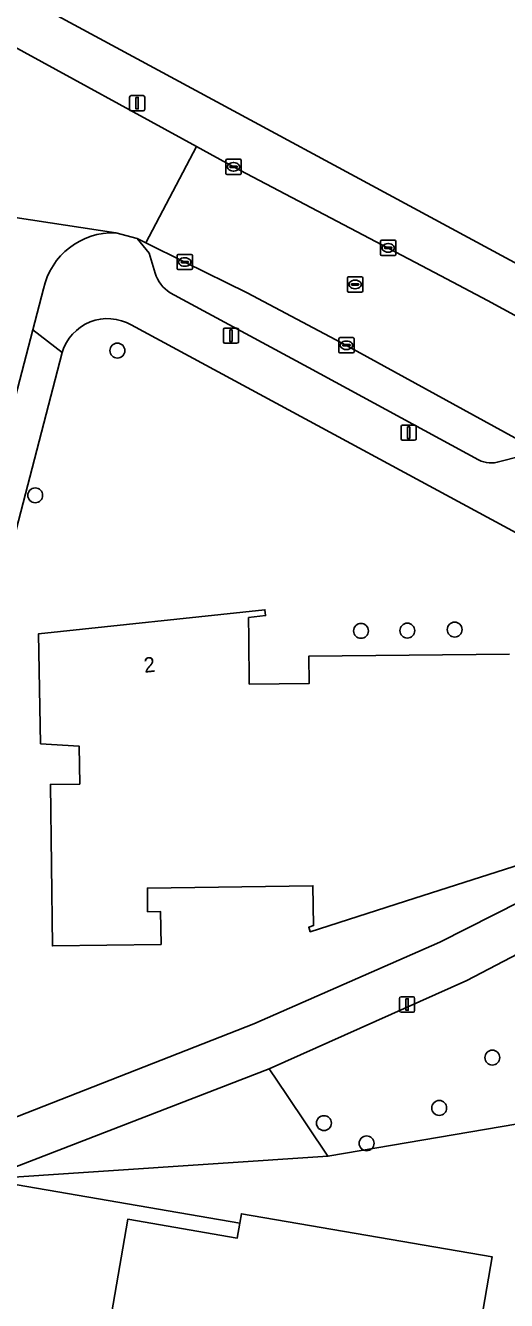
# Model space of a CAD drawing. Extents: x 161258 to 161838, y 380833 to 381727.
# Drawn here: x 161624.3 to 161655.9, y 381007.6 to 381091.2 of the extents above; entities that cross this region are included whole.
import ezdxf

# ---------------------------------------------------------------- set-up
doc = ezdxf.new("R2010")
doc.units = 0
for name, color, linetype in [('IMGEO_Boom', 7, 'Continuous'), ('IMGEO_Erf', 7, 'Continuous'), ('IMGEO_Fietspad_gesloten', 7, 'Continuous'), ('IMGEO_Groenvoorziening', 7, 'Continuous'), ('IMGEO_Kolk', 7, 'Continuous'), ('IMGEO_Lichtmast', 7, 'Continuous'), ('IMGEO_Pand', 7, 'Continuous'), ('IMGEO_Pand_nummerreeks', 7, 'Continuous'), ('IMGEO_Pand_overbouw', 7, 'Continuous'), ('IMGEO_Parkeervlak_open', 7, 'Continuous'), ('IMGEO_Rijbaan_lokaal_open', 7, 'Continuous'), ('IMGEO_Rioolput', 7, 'Continuous'), ('IMGEO_Voetpad_open', 7, 'Continuous')]:
    doc.layers.add(name, color=color, linetype=linetype)

msp = doc.modelspace()

# ---------------------------------------------------------------- linework, layer by layer
at = {"layer": 'IMGEO_Boom'}
for centre in [(161630.384, 381069.91), (161624.985, 381060.41), (161646.377, 381051.519), (161649.42, 381051.535), (161652.532, 381051.604), (161655.003, 381023.517), (161651.513, 381020.212), (161643.944, 381019.216), (161646.745, 381017.89)]:
    msp.add_circle(centre, 0.489, dxfattribs=at)
at = {"layer": 'IMGEO_Erf'}
for points in [[(161599.292, 381107.15), (161603.367, 381104.463), (161608.252, 381101.703), (161676.825, 381064.703), (161683.729, 381060.833), (161686.794, 381059.495), (161691.724, 381057.608), (161696.114, 381056.287), (161709.767, 381053.57)], [(161675.471, 381050.931), (161664.588, 381056.855), (161662.556, 381054.709), (161631.294, 381071.59)], [(161626.757, 381069.781), (161616.62, 381030.824), (161615.408, 381026.168), (161614.162, 381021.378)], [(161662.306, 381037.947), (161649.92, 381033.973), (161643.044, 381031.769), (161642.947, 381032.074), (161643.261, 381032.174), (161643.217, 381034.788), (161632.354, 381034.635), (161632.37, 381033.087), (161633.22, 381033.1), (161633.254, 381030.942), (161626.113, 381030.848), (161625.982, 381041.445), (161627.912, 381041.469), (161627.879, 381043.946), (161625.335, 381044.112), (161625.192, 381051.313), (161640.074, 381052.905), (161640.116, 381052.521), (161639, 381052.39), (161639.011, 381051.044), (161639.037, 381048.03), (161642.977, 381048.072), (161642.958, 381049.862), (161656.14, 381049.999)], [(161688.26, 381045.583), (161687.06, 381041.825), (161684.086, 381036.733), (161672.137, 381030.317), (161666.141, 381026.08), (161661.136, 381022.555), (161659.038, 381021.802), (161658.733, 381019.525), (161644.202, 381017.041), (161621.594, 381015.546), (161621.493, 381015.508), (161609.322, 381011.183), (161608.503, 381011.142), (161603.457, 381003.135)], [(161621.073, 381018.632), (161622.189, 381019.011), (161639.35, 381025.737), (161651.548, 381031.097), (161656.876, 381033.773)], [(161630.098, 381007.334), (161631.061, 381012.91), (161638.251, 381011.67), (161638.42, 381012.654), (161638.525, 381013.267), (161654.985, 381010.445), (161649.385, 380977.871)]]:
    msp.add_lwpolyline(points, dxfattribs=at)
msp.add_arc((161629.736, 381068.903), 3.106, 59.89964, 163.57684, dxfattribs=at)
at = {"layer": 'IMGEO_Fietspad_gesloten'}
for points in [[(161630.283, 381077.643), (161623.675, 381078.64), (161622.285, 381073.268), (161614.192, 381041.977), (161611.518, 381032.045)], [(161614.41, 381031.306), (161624.834, 381071.281), (161625.531, 381073.954)]]:
    msp.add_lwpolyline(points, dxfattribs=at)
msp.add_arc((161630.103, 381072.97), 4.676, 87.79003, 167.85469, dxfattribs=at)
at = {"layer": 'IMGEO_Groenvoorziening'}
msp.add_lwpolyline([(161679.02, 381046.972), (161678.939, 381046.842), (161676.868, 381044.169), (161675.516, 381042.671), (161671.619, 381039.336), (161668.104, 381036.84), (161665.195, 381035.022), (161660.071, 381032.09), (161653.332, 381028.579), (161640.355, 381022.779), (161641.485, 381021.093), (161644.202, 381017.041), (161658.733, 381019.525), (161659.038, 381021.802), (161661.136, 381022.555), (161666.141, 381026.08), (161672.137, 381030.317), (161684.086, 381036.733)], dxfattribs=at)
msp.add_lwpolyline([(161641.485, 381021.093), (161640.355, 381022.779), (161621.594, 381015.546), (161644.202, 381017.041)], close=True, dxfattribs=at)
at = {"layer": 'IMGEO_Kolk'}
for p, q in [((161637.508, 381081.541), (161637.508, 381082.393)), ((161637.583, 381082.467), (161638.435, 381082.467)), ((161637.767, 381081.961), (161637.767, 381081.973)), ((161638.205, 381081.924), (161637.807, 381081.924)), ((161637.81, 381082.01), (161638.208, 381082.01)), ((161637.996, 381082.247), (161638.021, 381082.247)), ((161638.251, 381081.973), (161638.251, 381081.961)), ((161638.509, 381082.393), (161638.509, 381081.541)), ((161638.435, 381081.467), (161637.583, 381081.467)), ((161638.019, 381081.687), (161637.994, 381081.687)), ((161647.664, 381076.221), (161647.664, 381077.073)), ((161647.739, 381077.147), (161648.591, 381077.147)), ((161648.152, 381076.927), (161648.177, 381076.927)), ((161648.665, 381077.073), (161648.665, 381076.221)), ((161634.306, 381075.296), (161634.306, 381076.148)), ((161634.381, 381076.222), (161635.233, 381076.222)), ((161634.794, 381076.002), (161634.819, 381076.002)), ((161635.307, 381076.148), (161635.307, 381075.296)), ((161648.591, 381076.147), (161647.739, 381076.147)), ((161647.923, 381076.641), (161647.923, 381076.653)), ((161648.361, 381076.604), (161647.963, 381076.604)), ((161647.966, 381076.69), (161648.364, 381076.69)), ((161648.175, 381076.367), (161648.15, 381076.367)), ((161648.407, 381076.653), (161648.407, 381076.641)), ((161635.233, 381075.222), (161634.381, 381075.222)), ((161634.565, 381075.716), (161634.565, 381075.728)), ((161635.003, 381075.679), (161634.605, 381075.679)), ((161634.608, 381075.765), (161635.006, 381075.765)), ((161634.817, 381075.442), (161634.792, 381075.442)), ((161635.049, 381075.728), (161635.049, 381075.716)), ((161644.922, 381069.832), (161644.922, 381070.684)), ((161644.997, 381070.758), (161645.849, 381070.758)), ((161645.181, 381070.252), (161645.181, 381070.264)), ((161645.619, 381070.215), (161645.221, 381070.215)), ((161645.224, 381070.301), (161645.622, 381070.301)), ((161645.41, 381070.538), (161645.435, 381070.538)), ((161645.665, 381070.264), (161645.665, 381070.252)), ((161645.923, 381070.684), (161645.923, 381069.832)), ((161645.849, 381069.758), (161644.997, 381069.758)), ((161645.433, 381069.978), (161645.408, 381069.978))]:
    msp.add_line(p, q, dxfattribs=at)
for points in [[(161637.508, 381081.541), (161637.508, 381082.393)], [(161637.583, 381082.467), (161638.435, 381082.467)], [(161638.509, 381082.393), (161638.509, 381081.541)], [(161638.435, 381081.467), (161637.583, 381081.467)], [(161647.664, 381076.221), (161647.664, 381077.073)], [(161647.739, 381077.147), (161648.591, 381077.147)], [(161648.665, 381077.073), (161648.665, 381076.221)], [(161634.306, 381075.296), (161634.306, 381076.148)], [(161634.381, 381076.222), (161635.233, 381076.222)], [(161635.307, 381076.148), (161635.307, 381075.296)], [(161648.591, 381076.147), (161647.739, 381076.147)], [(161635.233, 381075.222), (161634.381, 381075.222)], [(161644.922, 381069.832), (161644.922, 381070.684)], [(161644.997, 381070.758), (161645.849, 381070.758)], [(161645.923, 381070.684), (161645.923, 381069.832)], [(161645.849, 381069.758), (161644.997, 381069.758)]]:
    msp.add_lwpolyline(points, dxfattribs=at)
for centre, radius, start, end in [((161637.585, 381082.391), 0.0765, 91.55205, 178.44795), ((161637.585, 381082.391), 0.0765, 91.55205, 178.44795), ((161637.807, 381081.97), 0.0403, 85.87752, 175.75265), ((161637.804, 381081.96), 0.0366, 178.93798, 274.71019), ((161638.208, 381081.967), 0.043, 264.86636, 352.45326), ((161638.212, 381081.972), 0.0386, 1.73085, 96.63898), ((161638.433, 381082.391), 0.0765, 1.55205, 88.44795), ((161638.433, 381082.391), 0.0765, 1.55205, 88.44795), ((161637.585, 381081.543), 0.0765, 181.55205, 268.44795), ((161637.585, 381081.543), 0.0765, 181.55205, 268.44795), ((161638.433, 381081.543), 0.0765, 271.55205, 358.44795), ((161638.433, 381081.543), 0.0765, 271.55205, 358.44795), ((161647.741, 381077.071), 0.0765, 91.55205, 178.44795), ((161647.741, 381077.071), 0.0765, 91.55205, 178.44795), ((161648.589, 381077.071), 0.0765, 1.55205, 88.44795), ((161648.589, 381077.071), 0.0765, 1.55205, 88.44795), ((161634.383, 381076.146), 0.0765, 91.55205, 178.44795), ((161634.383, 381076.146), 0.0765, 91.55205, 178.44795), ((161635.231, 381076.146), 0.0765, 1.55205, 88.44795), ((161635.231, 381076.146), 0.0765, 1.55205, 88.44795), ((161647.741, 381076.223), 0.0765, 181.55205, 268.44795), ((161647.741, 381076.223), 0.0765, 181.55205, 268.44795), ((161647.963, 381076.65), 0.0403, 85.87752, 175.75265), ((161647.96, 381076.64), 0.0366, 178.93798, 274.71019), ((161648.364, 381076.647), 0.043, 264.86636, 352.45326), ((161648.368, 381076.652), 0.0386, 1.73085, 96.63898), ((161648.589, 381076.223), 0.0765, 271.55205, 358.44795), ((161648.589, 381076.223), 0.0765, 271.55205, 358.44795), ((161634.383, 381075.298), 0.0765, 181.55205, 268.44795), ((161634.383, 381075.298), 0.0765, 181.55205, 268.44795), ((161634.605, 381075.725), 0.0403, 85.87752, 175.75265), ((161634.602, 381075.715), 0.0366, 178.93798, 274.71019), ((161635.006, 381075.722), 0.043, 264.86636, 352.45326), ((161635.01, 381075.727), 0.0386, 1.73085, 96.63898), ((161635.231, 381075.298), 0.0765, 271.55205, 358.44795), ((161635.231, 381075.298), 0.0765, 271.55205, 358.44795), ((161644.999, 381070.682), 0.0765, 91.55205, 178.44795), ((161644.999, 381070.682), 0.0765, 91.55205, 178.44795), ((161645.221, 381070.261), 0.0403, 85.87752, 175.75265), ((161645.218, 381070.251), 0.0366, 178.93798, 274.71019), ((161645.622, 381070.258), 0.043, 264.86636, 352.45326), ((161645.626, 381070.263), 0.0386, 1.73085, 96.63898), ((161645.847, 381070.682), 0.0765, 1.55205, 88.44795), ((161645.847, 381070.682), 0.0765, 1.55205, 88.44795), ((161644.999, 381069.834), 0.0765, 181.55205, 268.44795), ((161644.999, 381069.834), 0.0765, 181.55205, 268.44795), ((161645.847, 381069.834), 0.0765, 271.55205, 358.44795), ((161645.847, 381069.834), 0.0765, 271.55205, 358.44795)]:
    msp.add_arc(centre, radius, start, end, dxfattribs=at)
for centre, major_axis, ratio, start_param, end_param in [((161637.995, 381081.967), (-0.387, 0.002), 0.722429, 4.712389, 7.853982), ((161638.02, 381081.967), (-0.39, 0.002), 0.717154, 1.570796, 4.712389), ((161648.151, 381076.647), (-0.387, 0.002), 0.722429, 4.712389, 7.853982), ((161648.176, 381076.647), (-0.39, 0.002), 0.717154, 1.570796, 4.712389), ((161634.793, 381075.722), (-0.387, 0.002), 0.722429, 4.712389, 7.853982), ((161634.818, 381075.722), (-0.39, 0.002), 0.717154, 1.570796, 4.712389), ((161645.409, 381070.258), (-0.387, 0.002), 0.722429, 4.712389, 7.853982), ((161645.434, 381070.258), (-0.39, 0.002), 0.717154, 1.570796, 4.712389)]:
    msp.add_ellipse(centre, major_axis=major_axis, ratio=ratio, start_param=start_param, end_param=end_param, dxfattribs=at)
at = {"layer": 'IMGEO_Lichtmast'}
for p, q in [((161631.184, 381085.743), (161631.184, 381086.543)), ((161631.184, 381086.543), (161631.184, 381085.743)), ((161631.284, 381086.643), (161632.074, 381086.643)), ((161632.074, 381086.643), (161631.284, 381086.643)), ((161632.174, 381086.543), (161632.174, 381085.743)), ((161632.174, 381085.743), (161632.174, 381086.543)), ((161632.074, 381085.643), (161631.284, 381085.643)), ((161631.284, 381085.643), (161632.074, 381085.643)), ((161637.342, 381070.488), (161637.342, 381071.288)), ((161637.342, 381071.288), (161637.342, 381070.488)), ((161637.442, 381071.388), (161638.232, 381071.388)), ((161638.232, 381071.388), (161637.442, 381071.388)), ((161638.332, 381071.288), (161638.332, 381070.488)), ((161638.332, 381070.488), (161638.332, 381071.288)), ((161638.232, 381070.388), (161637.442, 381070.388)), ((161637.442, 381070.388), (161638.232, 381070.388)), ((161649.011, 381064.121), (161649.011, 381064.921)), ((161649.011, 381064.921), (161649.011, 381064.121)), ((161649.111, 381065.021), (161649.901, 381065.021)), ((161649.901, 381065.021), (161649.111, 381065.021)), ((161650.001, 381064.921), (161650.001, 381064.121)), ((161650.001, 381064.121), (161650.001, 381064.921)), ((161649.901, 381064.021), (161649.111, 381064.021)), ((161649.111, 381064.021), (161649.901, 381064.021)), ((161649.011, 381027.5), (161649.801, 381027.5)), ((161649.801, 381027.5), (161649.011, 381027.5)), ((161648.911, 381026.6), (161648.911, 381027.4)), ((161648.911, 381027.4), (161648.911, 381026.6)), ((161649.901, 381027.4), (161649.901, 381026.6)), ((161649.901, 381026.6), (161649.901, 381027.4)), ((161649.801, 381026.5), (161649.011, 381026.5)), ((161649.011, 381026.5), (161649.801, 381026.5))]:
    msp.add_line(p, q, dxfattribs=at)
for points in [[(161631.604, 381086.518), (161631.754, 381086.518), (161631.754, 381085.768), (161631.604, 381085.768), (161631.604, 381086.518)], [(161637.762, 381071.263), (161637.912, 381071.263), (161637.912, 381070.513), (161637.762, 381070.513), (161637.762, 381071.263)], [(161649.431, 381064.896), (161649.581, 381064.896), (161649.581, 381064.146), (161649.431, 381064.146), (161649.431, 381064.896)], [(161649.331, 381027.375), (161649.481, 381027.375), (161649.481, 381026.625), (161649.331, 381026.625), (161649.331, 381027.375)]]:
    msp.add_lwpolyline(points, dxfattribs=at)
for centre, start, end in [((161631.284, 381086.543), 90, 180), ((161631.284, 381086.543), 90, 180), ((161632.074, 381086.543), 0, 90), ((161632.074, 381086.543), 360, 90), ((161631.284, 381085.743), 180, 270), ((161631.284, 381085.743), 180, 270), ((161632.074, 381085.743), 270, 0), ((161632.074, 381085.743), 270, 0), ((161637.442, 381071.288), 90, 180), ((161637.442, 381071.288), 90, 180), ((161638.232, 381071.288), 0, 90), ((161638.232, 381071.288), 360, 90), ((161637.442, 381070.488), 180, 270), ((161637.442, 381070.488), 180, 270), ((161638.232, 381070.488), 270, 0), ((161638.232, 381070.488), 270, 0), ((161649.111, 381064.921), 90, 180), ((161649.111, 381064.921), 90, 180), ((161649.901, 381064.921), 0, 90), ((161649.901, 381064.921), 360, 90), ((161649.111, 381064.121), 180, 270), ((161649.111, 381064.121), 180, 270), ((161649.901, 381064.121), 270, 0), ((161649.901, 381064.121), 270, 0), ((161649.011, 381027.4), 90, 180), ((161649.011, 381027.4), 90, 180), ((161649.801, 381027.4), 0, 90), ((161649.801, 381027.4), 360, 90), ((161649.011, 381026.6), 180, 270), ((161649.011, 381026.6), 180, 270), ((161649.801, 381026.6), 270, 0), ((161649.801, 381026.6), 270, 0)]:
    msp.add_arc(centre, 0.1, start, end, dxfattribs=at)
at = {"layer": 'IMGEO_Pand'}
msp.add_lwpolyline([(161656.14, 381049.999), (161642.958, 381049.862), (161642.977, 381048.072), (161639.037, 381048.03), (161639.011, 381051.044), (161639, 381052.39), (161640.116, 381052.521), (161640.074, 381052.905), (161625.192, 381051.313), (161625.335, 381044.112), (161627.879, 381043.946), (161627.912, 381041.469), (161625.982, 381041.445), (161626.113, 381030.848), (161633.254, 381030.942), (161633.22, 381033.1), (161632.37, 381033.087), (161632.354, 381034.635), (161643.217, 381034.788), (161643.261, 381032.174), (161642.947, 381032.074), (161643.044, 381031.769), (161649.92, 381033.973), (161662.306, 381037.947)], dxfattribs=at)
msp.add_lwpolyline([(161647.439, 380966.629), (161648.17, 380970.892), (161648.549, 380973.103), (161651.15, 380972.652), (161651.976, 380977.422), (161651.777, 380977.456), (161649.385, 380977.871), (161654.985, 381010.445), (161638.525, 381013.267), (161638.42, 381012.654), (161638.251, 381011.67), (161631.061, 381012.91), (161630.098, 381007.334), (161629.73, 381005.204), (161629.086, 381001.476), (161636.289, 381000.232), (161632.862, 380980.375), (161632.828, 380980.176), (161632.345, 380977.38), (161632.262, 380976.901), (161630.974, 380969.465), (161632.027, 380969.284)], close=True, dxfattribs=at)
at = {"layer": 'IMGEO_Pand_overbouw'}
msp.add_lwpolyline([(161630.098, 381007.334), (161631.061, 381012.91), (161638.251, 381011.67), (161638.42, 381012.654), (161599.744, 381019.301), (161595.349, 381020.056), (161587.915, 381021.334), (161579.647, 381022.757), (161571.38, 381024.181), (161568.164, 381024.732), (161546.929, 381028.397), (161543.554, 381028.979), (161529.957, 381031.314), (161529.713, 381031.356), (161529.469, 381031.398), (161494.957, 381037.336)], dxfattribs=at)
at = {"layer": 'IMGEO_Parkeervlak_open'}
for points in [[(161658.944, 381062.836), (161645.436, 381070.252), (161638.895, 381073.701), (161634.807, 381075.723), (161632.244, 381076.986), (161631.678, 381077.263), (161632.464, 381076.312), (161632.865, 381074.999)], [(161633.849, 381073.709), (161642.932, 381068.81), (161654.103, 381062.734)], [(161655.5, 381062.629), (161656.781, 381062.954)]]:
    msp.add_lwpolyline(points, dxfattribs=at)
for centre, radius, start, end in [((161634.97, 381075.584), 2.185, 195.53739, 239.13472), ((161654.927, 381064.348), 1.812, 242.95635, 288.44699)]:
    msp.add_arc(centre, radius, start, end, dxfattribs=at)
at = {"layer": 'IMGEO_Rijbaan_lokaal_open'}
for points in [[(161622.315, 381078.834), (161623.675, 381078.64), (161630.283, 381077.643), (161631.678, 381077.263), (161632.244, 381076.986), (161635.58, 381083.294), (161623.338, 381089.989), (161611.018, 381096.621), (161607.745, 381090.263), (161608.262, 381090.01), (161609.367, 381089.192)], [(161685.459, 381056.689), (161680.698, 381058.941), (161677.177, 381060.856), (161669.88, 381065.045), (161664.516, 381067.867), (161654.689, 381073.206), (161651.628, 381074.813), (161638.009, 381081.966), (161635.58, 381083.294), (161632.244, 381076.986), (161634.807, 381075.723), (161638.895, 381073.701), (161645.436, 381070.252), (161658.944, 381062.836), (161666.013, 381059.008), (161667.897, 381057.988), (161670.17, 381056.699), (161670.707, 381056.408), (161674.187, 381054.522), (161677.079, 381052.97), (161679.132, 381051.841)]]:
    msp.add_lwpolyline(points, dxfattribs=at)
at = {"layer": 'IMGEO_Rioolput'}
for p, q in [((161645.493, 381073.825), (161645.493, 381074.677)), ((161645.568, 381074.751), (161646.42, 381074.751)), ((161645.981, 381074.531), (161646.006, 381074.531)), ((161646.494, 381074.677), (161646.494, 381073.825)), ((161646.42, 381073.751), (161645.568, 381073.751)), ((161645.752, 381074.245), (161645.752, 381074.257)), ((161646.19, 381074.208), (161645.792, 381074.208)), ((161645.795, 381074.294), (161646.193, 381074.294)), ((161646.004, 381073.971), (161645.979, 381073.971)), ((161646.236, 381074.257), (161646.236, 381074.245))]:
    msp.add_line(p, q, dxfattribs=at)
for points in [[(161645.493, 381073.825), (161645.493, 381074.677)], [(161645.568, 381074.751), (161646.42, 381074.751)], [(161646.494, 381074.677), (161646.494, 381073.825)], [(161646.42, 381073.751), (161645.568, 381073.751)]]:
    msp.add_lwpolyline(points, dxfattribs=at)
for centre, radius, start, end in [((161645.57, 381074.675), 0.0765, 91.55205, 178.44795), ((161645.57, 381074.675), 0.0765, 91.55205, 178.44795), ((161646.418, 381074.675), 0.0765, 1.55205, 88.44795), ((161646.418, 381074.675), 0.0765, 1.55205, 88.44795), ((161645.57, 381073.827), 0.0765, 181.55205, 268.44795), ((161645.57, 381073.827), 0.0765, 181.55205, 268.44795), ((161645.792, 381074.254), 0.0403, 85.87752, 175.75265), ((161645.789, 381074.244), 0.0366, 178.93798, 274.71019), ((161646.193, 381074.251), 0.043, 264.86636, 352.45326), ((161646.197, 381074.256), 0.0386, 1.73085, 96.63898), ((161646.418, 381073.827), 0.0765, 271.55205, 358.44795), ((161646.418, 381073.827), 0.0765, 271.55205, 358.44795)]:
    msp.add_arc(centre, radius, start, end, dxfattribs=at)
for centre, major_axis, ratio, start_param, end_param in [((161645.98, 381074.251), (-0.387, 0.002), 0.722429, 4.712389, 7.853982), ((161646.005, 381074.251), (-0.39, 0.002), 0.717154, 1.570796, 4.712389)]:
    msp.add_ellipse(centre, major_axis=major_axis, ratio=ratio, start_param=start_param, end_param=end_param, dxfattribs=at)
at = {"layer": 'IMGEO_Voetpad_open'}
for points in [[(161598.405, 381103.885), (161602.607, 381101.294), (161602.851, 381101.158), (161607.838, 381098.385), (161610.746, 381096.768), (161611.018, 381096.621), (161623.338, 381089.989), (161635.58, 381083.294), (161638.009, 381081.966), (161651.628, 381074.813), (161654.689, 381073.206), (161664.516, 381067.867), (161669.88, 381065.045), (161677.177, 381060.856), (161680.698, 381058.941), (161685.459, 381056.689), (161686.794, 381059.495), (161683.729, 381060.833), (161676.825, 381064.703), (161608.252, 381101.703)], [(161632.865, 381074.999), (161632.464, 381076.312), (161631.678, 381077.263), (161630.283, 381077.643)], [(161625.531, 381073.954), (161624.834, 381071.281), (161626.757, 381069.781)], [(161654.103, 381062.734), (161642.932, 381068.81), (161633.849, 381073.709)], [(161631.294, 381071.59), (161662.556, 381054.709), (161664.588, 381056.855), (161675.471, 381050.931), (161682.316, 381047.794), (161684.449, 381046.924), (161688.26, 381045.583), (161691.047, 381044.602), (161693.931, 381043.708), (161696.121, 381043.204), (161710.784, 381040.897), (161712.11, 381042.229)], [(161656.781, 381062.954), (161655.5, 381062.629)], [(161614.162, 381021.378), (161608.503, 381011.142), (161609.322, 381011.183), (161621.493, 381015.508), (161621.594, 381015.546), (161640.355, 381022.779), (161653.332, 381028.579), (161660.071, 381032.09), (161665.195, 381035.022), (161668.104, 381036.84), (161671.619, 381039.336), (161675.516, 381042.671)], [(161656.876, 381033.773), (161651.548, 381031.097), (161639.35, 381025.737), (161622.189, 381019.011), (161621.073, 381018.632)]]:
    msp.add_lwpolyline(points, dxfattribs=at)
msp.add_lwpolyline([(161626.757, 381069.781), (161624.834, 381071.281), (161614.41, 381031.306), (161616.62, 381030.824)], close=True, dxfattribs=at)
for centre, radius, start, end in [((161630.103, 381072.97), 4.676, 87.79003, 167.85469), ((161634.97, 381075.584), 2.185, 195.53739, 239.13472), ((161629.736, 381068.903), 3.106, 59.89964, 163.57684), ((161654.927, 381064.348), 1.812, 242.95635, 288.44699)]:
    msp.add_arc(centre, radius, start, end, dxfattribs=at)

# ---------------------------------------------------------------- texts
at = {"layer": 'IMGEO_Pand_nummerreeks'}
msp.add_text('2', height=1, rotation=6.10621, dxfattribs=at).set_placement((161632.168, 381048.761))

doc.saveas('drawing.dxf')
